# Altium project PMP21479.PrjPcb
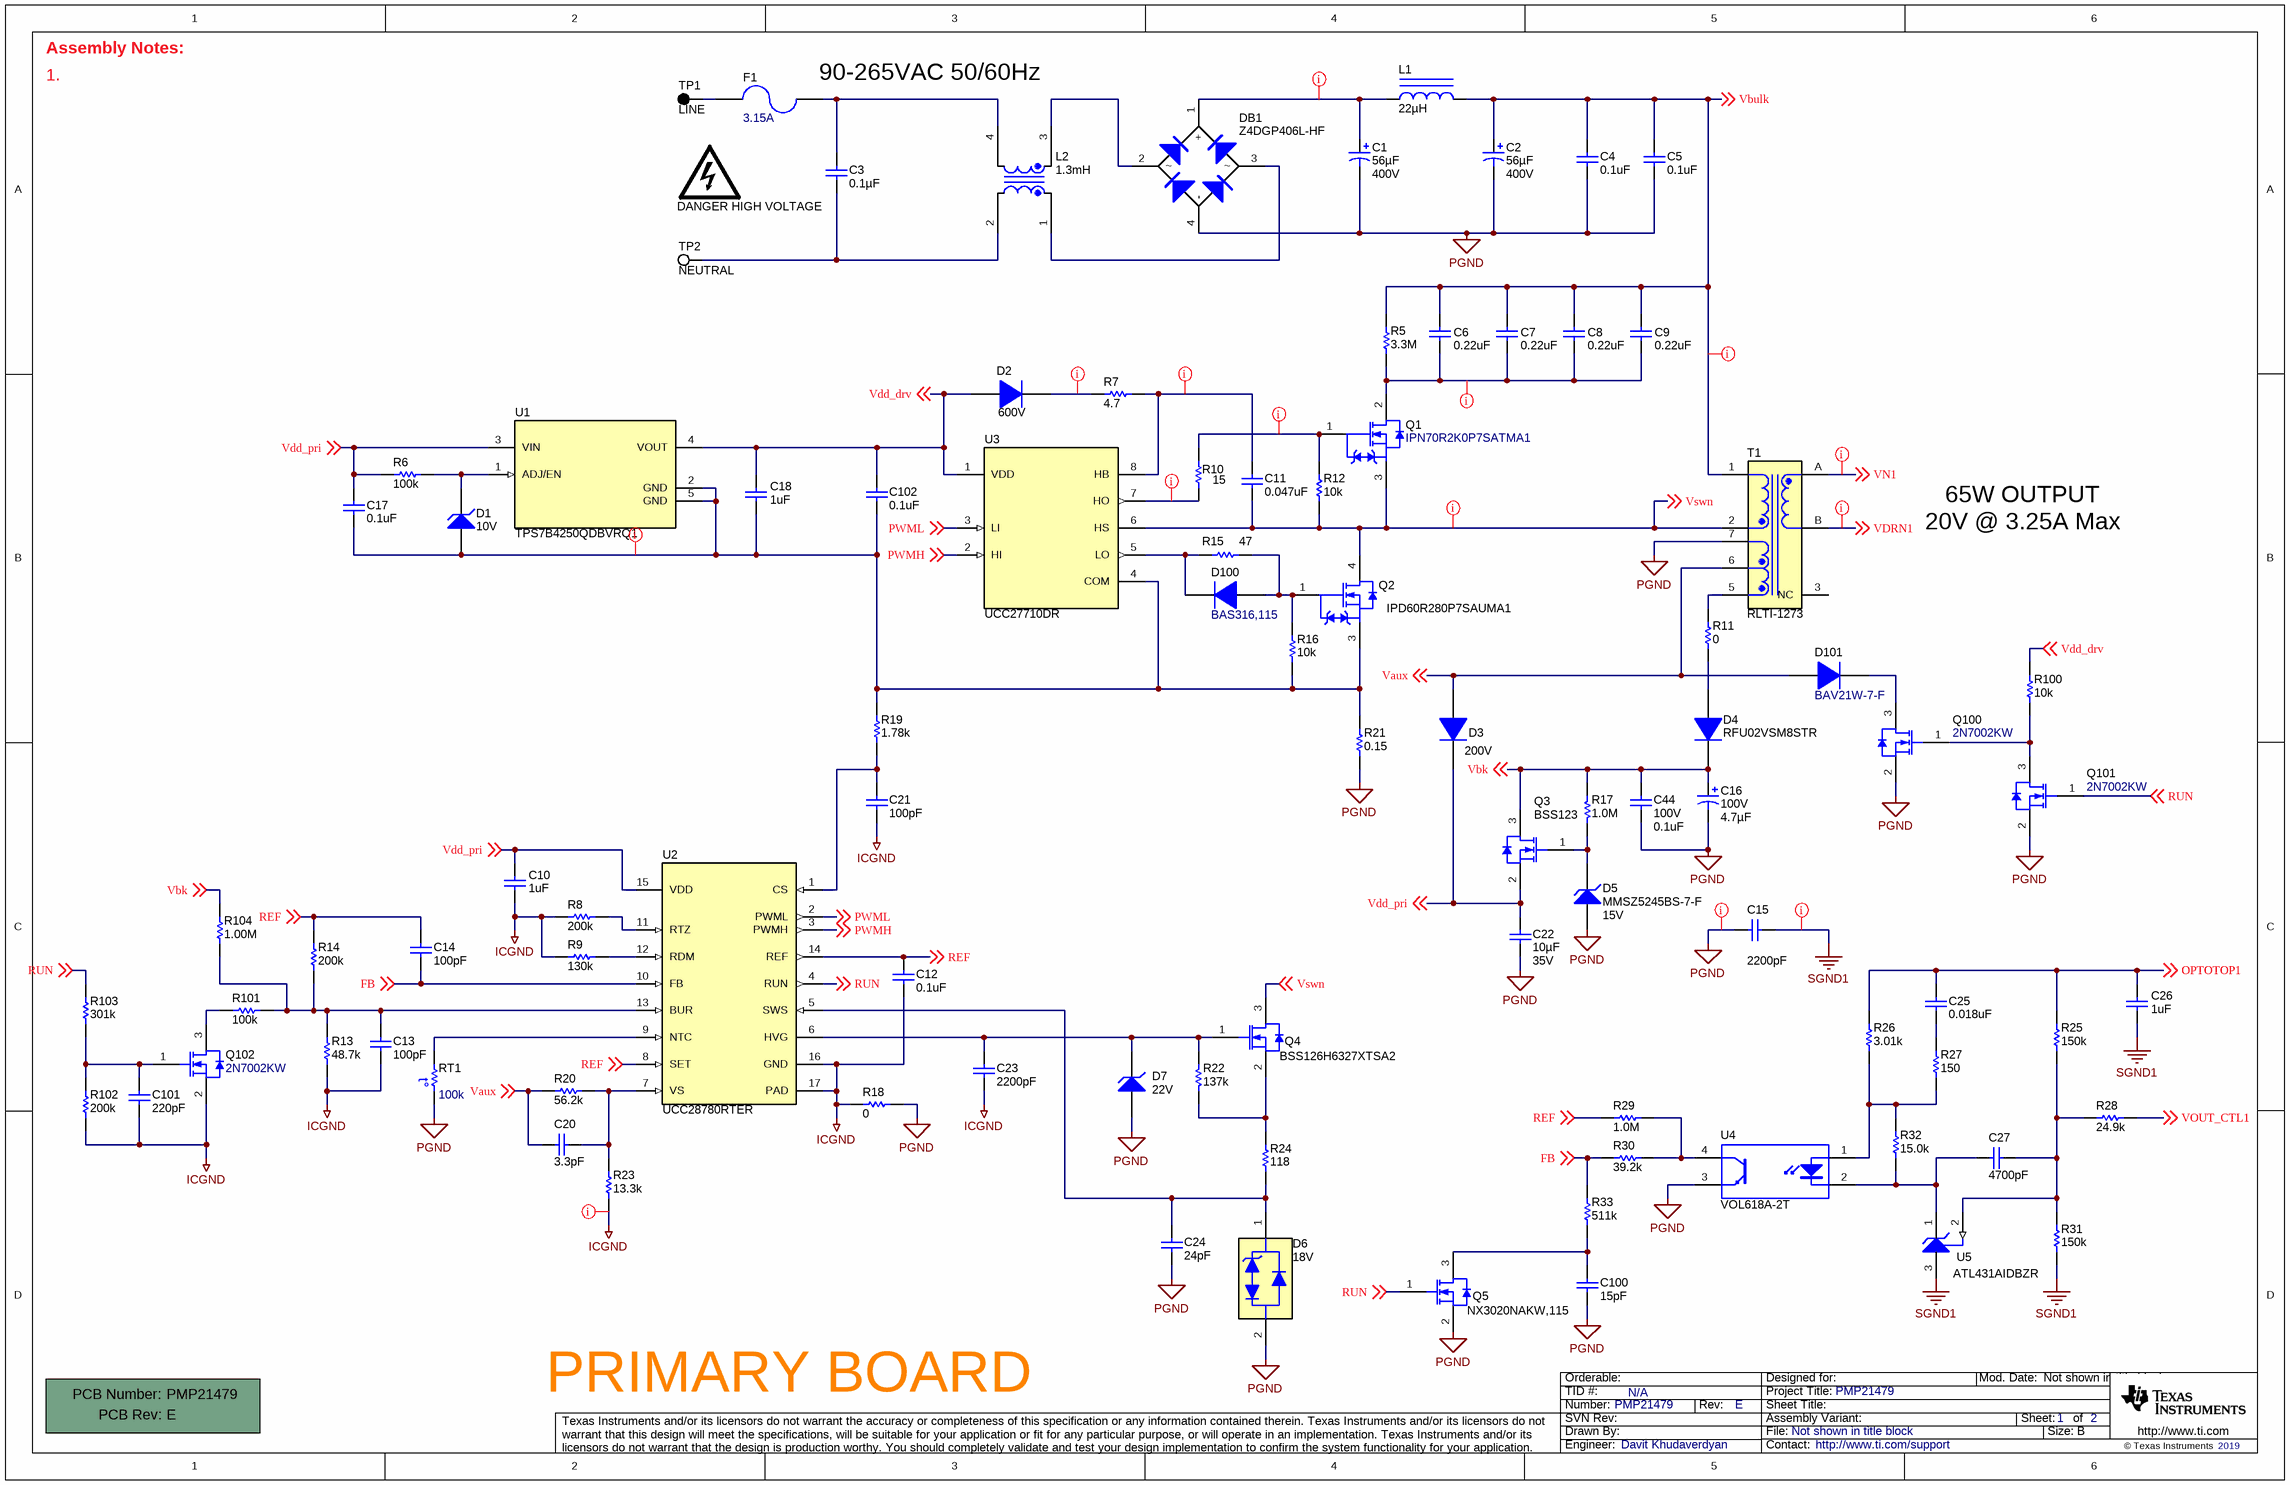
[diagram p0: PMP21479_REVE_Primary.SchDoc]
CopyrightYear: 2019; PCB_Layout: B King; PCB_Rev: E; PRJ_Engineer: Davit Khudaverdyan; PRJ_Number: PMP21479; PRJ_Title: PMP21479; SCH_Rev: E; TechSupport: http://www.ti.com/support; TID: N/A
2 sheets, 138 parts. Net scope: global (net labels, ports and power ports of the same name join across sheets).
Board file: PMP21479_PCBREVE.PcbDoc
Sheets:
  PMP21479_REVE_Primary.SchDoc
  PMP21479_REVE_Secondary.SchDoc

## Sheet PMP21479_REVE_Primary.SchDoc
size 431 x 279 mm; Date: Not shown in title block; ApprovedBy: Not shown in title block; CheckedBy: Not shown in title block; Author: Not shown in title block; CompanyName: Not shown in title block; Engineer: Not shown in title block; Organization: Not shown in title block; Address1: Not shown in title block; Address2: Not shown in title block; Address3: Not shown in title block; Address4: Not shown in title block; DocumentNumber: 1; Revision: Use project parameter SCH_Rev; SheetNumber: 1; SheetTotal: 2; PageSetup: Record=PageOptions¦CenterHorizontal=True¦CenterVertical=True¦PrintScale=1.00¦XCorrection=1.00¦YCorrection=1.00¦PrintKind=0¦BorderSize=5000000¦LeftOffset=0¦BottomOffset=0¦Orientation=2¦PaperLength=1000¦PaperWidth=1000¦Scale=100¦PaperSource=15¦PrintQuality=600¦MediaType=1¦DitherType=10¦PaperKind=Letter¦PrintScaleMode=1

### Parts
!PCB1  Printed Circuit Board  (value not drawn)  (mechanical)
C1  ValueDisplayed: 56µF  VDC_V: 400V  [UCY_1800x2000]  (hidden comment: UCY2G560MHD3)
C2  ValueDisplayed: 56µF  VDC_V: 400V  [UCY_1800x2000]  (hidden comment: UCY2G560MHD3)
C3  ValueDisplayed: 0.1µF  [WCAP-FTX2_1300x700x1300]  (hidden comment: 890324023023)
C4  ValueDisplayed: 0.1uF  [1210_280]  (hidden comment: C1210C104KBRAC7800)
C5  ValueDisplayed: 0.1uF  [1210_280]  (hidden comment: C1210C104KBRAC7800)
C6  ValueDisplayed: 0.22uF  [1210_220L]  (hidden comment: GRM32DR72E224KW01L)
C7  ValueDisplayed: 0.22uF  [1210_220L]  (hidden comment: GRM32DR72E224KW01L)
C8  ValueDisplayed: 0.22uF  [1210_220L]  (hidden comment: GRM32DR72E224KW01L)
C9  ValueDisplayed: 0.22uF  [1210_220L]  (hidden comment: GRM32DR72E224KW01L)
C10  ValueDisplayed: 1uF  [0603S]  (hidden comment: C1608X7R1E105K080AB)
C11  ValueDisplayed: 0.047uF  [0603S]  (hidden comment: GRM188R71E473KA01D)
C12  ValueDisplayed: 0.1uF  [0402S]  (hidden comment: C1005X7R1H104K050BB)
C13  ValueDisplayed: 100pF  [0402L]  (hidden comment: GRM1555C1H101JA01D)
C14  ValueDisplayed: 100pF  [0402L]  (hidden comment: GRM1555C1H101JA01D)
C15  ValueDisplayed: 2200pF  [DE1_900x400]  (hidden comment: DE1E3RA222MN4AN01F)
C16  VDC_V: 100V  ValueDisplayed: 4.7µF  [UPW_500x1100]  (hidden comment: UPS2A4R7MDD1TD)
C17  ValueDisplayed: 0.1uF  [0402S]  (hidden comment: GRM155R71E104KE14D)
C18  ValueDisplayed: 1uF  [0603S]  (hidden comment: C1608X7R1E105K080AB)
C20  ValueDisplayed: 3.3pF  [0402S]  (hidden comment: GRM1555C1H3R3CA01D)
C21  ValueDisplayed: 100pF  [0402L]  (hidden comment: GRM1555C1H101JA01D)
C22  ValueDisplayed: 10µF  Value2: 35V  [0805L]  (hidden comment: GRM21BC8YA106KE11L)
C23  ValueDisplayed: 2200pF  [0402S]  (hidden comment: GRM155R71H222KA01D)
C24  ValueDisplayed: 24pF  [0402S]  (hidden comment: GRM1555C1H240JA01D)
C25  ValueDisplayed: 0.018uF  [0402S]  (hidden comment: GRM155R71H183KA12D)
C26  ValueDisplayed: 1uF  [0603S]  (hidden comment: C1608X7R1E105K080AB)
C27  ValueDisplayed: 4700pF  [0402S]  (hidden comment: GRM155R71H472KA01D)
C44  VDC_V: 100V  ValueDisplayed: 0.1uF  [1206L]  (hidden comment: 12061C104JAT2A)
C100  ValueDisplayed: 15pF  [0402L]  (hidden comment: GRM1555C1H150JA01D)
C101  ValueDisplayed: 220pF  [0402L]  (hidden comment: GRM1555C1H221JA01D)
C102  ValueDisplayed: 0.1uF  [0402S]  (hidden comment: GRM155R71E104KE14D)
D1  value 10V  [SOD-323]  (hidden comment: MMSZ5240BS-7-F)
D2  value 600V  [SMAF]  (hidden comment: ES1JAF)
D3  value 200V  [SOD-123H]  (hidden comment: CSFMT104-HF)
D4  RFU02VSM8STR  [TUMD2SM]
D5  MMSZ5245BS-7-F  value 15V  [SOD-323]
D6  value 18V  [SOD-323]  (hidden comment: CDSOD323-T18)
D7  value 22V  [SOD-523]  (hidden comment: BZT52C22T-7)
D100  BAS316,115  [SOD-323]
D101  BAV21W-7-F  [SOD-123]
DB1  Z4DGP406L-HF  [Z4-D]
F1  3.15A  [FUSE_392]
L1  ValueDisplayed: 22µH  [NRS8030]  (hidden comment: NRS8030T220MJGJ)
L2  ValueDisplayed: 1.3mH  [Renco_RLTI-1301]  (hidden comment: RLTI-1301)
LOGO1  DANGER HIGH VOLTAGE  [IEC_HighVoltage_Small]  (no BOM)
Q1  IPN70R2K0P7SATMA1  [PG-SOT223]
Q2  IPD60R280P7SAUMA1  [DPAK]
Q3  BSS123  [SOT-23L]
Q4  BSS126H6327XTSA2  [SOT-23L]
Q5  NX3020NAKW,115  [SOT-323]
Q100  2N7002KW  [SOT-323]
Q101  2N7002KW  [SOT-323]
Q102  2N7002KW  [SOT-323]
R5  ValueDisplayed: 3.3M  [1206L]  (hidden comment: CRCW12063M30JNEA)
R6  ValueDisplayed: 100k  [0402L]  (hidden comment: RC0402FR-07100KL)
R7  ValueDisplayed: 4.7  [0402S]  (hidden comment: CRCW04024R70JNED)
R8  ValueDisplayed: 200k  [0402L]  (hidden comment: CRCW0402200KFKED)
R9  ValueDisplayed: 130k  [0402L]  (hidden comment: CRCW0402130KFKED)
R10  ValueDisplayed: 15  [0402S]  (hidden comment: CRCW040215R0JNED)
R11  ValueDisplayed: 0  [0402S]  (hidden comment: CRCW04020000Z0ED)
R12  ValueDisplayed: 10k  [0402S]  (hidden comment: CRCW040210K0JNED)
R13  ValueDisplayed: 48.7k  [0402L]  (hidden comment: CRCW040248K7FKED)
R14  ValueDisplayed: 200k  [0402L]  (hidden comment: CRCW0402200KFKED)
R15  ValueDisplayed: 47  [0805L]  (hidden comment: CRCW080547R0JNEA)
R16  ValueDisplayed: 10k  [0402S]  (hidden comment: CRCW040210K0JNED)
R17  ValueDisplayed: 1.0M  [0402S]  (hidden comment: CRCW04021M00JNED)
R18  ValueDisplayed: 0  [0402S]  (hidden comment: CRCW04020000Z0ED)
R19  ValueDisplayed: 1.78k  [0402S]  (hidden comment: CRCW04021K78FKED)
R20  ValueDisplayed: 56.2k  [0402S]  (hidden comment: CRCW040256K2FKED)
R21  ValueDisplayed: 0.15  [1206L]  (hidden comment: ERJ-8BSFR15V)
R22  ValueDisplayed: 137k  [0402S]  (hidden comment: ERJ-2RKF1373X)
R23  ValueDisplayed: 13.3k  [0402S]  (hidden comment: CRCW040213K3FKED)
R24  ValueDisplayed: 118  [0402S]  (hidden comment: CRCW0402118RFKED)
R25  ValueDisplayed: 150k  [0402S]  (hidden comment: ERJ-2RKF1503X)
R26  ValueDisplayed: 3.01k  [0402S]  (hidden comment: CRCW04023K01FKED)
R27  ValueDisplayed: 150  [0402S]  (hidden comment: CRCW0402150RFKED)
R28  ValueDisplayed: 24.9k  [0402S]  (hidden comment: CRCW040224K9FKED)
R29  ValueDisplayed: 1.0M  [0402S]  (hidden comment: CRCW04021M00JNED)
R30  ValueDisplayed: 39.2k  [0402S]  (hidden comment: CRCW040239K2FKED)
R31  ValueDisplayed: 150k  [0402S]  (hidden comment: ERJ-2RKF1503X)
R32  ValueDisplayed: 15.0k  [0402S]  (hidden comment: CRCW040215K0FKED)
R33  ValueDisplayed: 511k  [0402S]  (hidden comment: CRCW0402511KFKED)
R100  ValueDisplayed: 10k  [0402S]  (hidden comment: CRCW040210K0JNED)
R101  ValueDisplayed: 100k  [0402L]  (hidden comment: CRCW0402100KFKED)
R102  ValueDisplayed: 200k  [0402L]  (hidden comment: CRCW0402200KFKED)
R103  ValueDisplayed: 301k  [0402L]  (hidden comment: CRCW0402301KFKED)
R104  ValueDisplayed: 1.00M  [0402L]  (hidden comment: CRCW04021M00FKED)
RT1  value 100k  [0805L]  (hidden comment: NCP21WF104J03RA)
T1  RLTI-1273  [Renco_RLTI-1273]
TP1  LINE  [Keystone5011]
TP2  NEUTRAL  [Keystone5012]
U1  TPS7B4250QDBVRQ1  [DBV0005A_N]
U2  UCC28780RTER  [RTE0016C_NV]
U3  UCC27710DR  [D0008B_L]
U4  VOL618A-2T  [SOP254P1020X230-4]
U5  ATL431AIDBZR  [DBZ0003A_L]

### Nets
ICGND: C10.2 C12.2 C13.2 C21.2 C23.2 C101.2 Q102.2(S) R8.1 R9.1 R13.1 R18.2 R23.1 R102.1 U2.16(GND) U2.17(PAD)
PGND: C1.2(-) C2.2(-) C4.1 C5.1 C15.2 C16.2(-) C22.1 C24.1 C44.2 C100.2 D5.2(A) D6.2 D7.2(A) DB1.4(-) Q5.2(S) Q100.2(S) Q101.2(S) R18.1 R21.1 RT1.2 T1.7 U4.3(E)
SGND1: C15.1 C26.1 R31.2 U5.3(ANODE)
FB: C14.2 R30.1 R33.2 U2.10(FB) ; off-sheet FB
OPTOTOP1: C25.1 C26.2 R25.2 R26.2 ; off-sheet OPTOTOP1
PWMH: U2.3(PWMH) U3.2(HI) ; off-sheet PWMH
PWML: U2.2(PWML) U3.3(LI) ; off-sheet PWML
REF: C12.1 C14.1 R14.2 R29.2 U2.8(SET) U2.14(REF) ; off-sheet REF
RUN: Q5.1(G) Q101.1(G) R103.2 U2.4(RUN) ; off-sheet RUN
Vaux: C20.1 D3.2(A) D101.2(A) R20.2 T1.6 ; off-sheet Vaux
Vbk: C16.1(+) C44.1 D4.1(K) Q3.3(D) R17.1 R104.2 ; off-sheet Vbk
Vbulk: C2.1(+) C4.2 C5.2 C6.1 C7.1 C8.1 C9.1 L1.2 R5.2 T1.1 ; off-sheet Vbulk
Vdd_drv: C18.2 C102.1 D2.2(A) R100.2 U1.4(VOUT) U3.1(VDD) ; off-sheet Vdd_drv
Vdd_pri: C10.1 C17.1 C22.2 D3.1(K) Q3.2(S) R6.2 U1.3(VIN) U2.15(VDD) ; off-sheet Vdd_pri
VDRN1: T1.B ; off-sheet VDRN1
VN1: T1.A ; off-sheet VN1
VOUT_CTL1: R28.1 ; off-sheet VOUT_CTL1
Vswn: C11.2 Q1.3(S) Q2.4(D) Q4.3(D) R12.1 T1.2 U3.6(HS) ; off-sheet Vswn
NetC1_1: C1.1(+) DB1.1(+) L1.1
NetC3_1: C3.1 F1.1 L2.4
NetC3_2: C3.2 L2.2 TP2.1
NetC6_2: C6.2 C7.2 C8.2 C9.2 Q1.2(D) R5.1
NetC11_1: C11.1 R7.2 U3.8(HB)
NetC13_1: C13.1 R13.2 R14.1 R101.2 R104.1 U2.13(BUR)
NetC17_2: C17.2 C18.1 C102.2 D1.2(A) Q2.3(S) R16.1 R19.2 R21.2 U1.2(GND) U1.5(GND) U3.4(COM)
NetC20_2: C20.2 R20.1 R23.2 U2.7(VS)
NetC21_1: C21.1 R19.1 U2.1(CS)
NetC23_1: C23.1 D7.1(K) Q4.1(G) R22.2 U2.6(HVG)
NetC24_2: C24.2 D6.1 R24.1 U2.5(SWS)
NetC25_2: C25.2 R27.2
NetC27_1: C27.1 R25.1 R28.2 R31.1 U5.2(REF)
NetC27_2: C27.2 R32.1 U4.2(K) U5.1(CATHODE)
NetC100_1: C100.1 Q5.3(D) R33.1
NetC101_1: C101.1 Q102.1(G) R102.2 R103.1
NetD1_1: D1.1(K) R6.1 U1.1(ADJ/EN)
NetD2_1: D2.1(K) R7.1
NetD4_2: D4.2(A) R11.2
NetD5_1: D5.1(K) Q3.1(G) R17.2
NetD100_1: D100.1(K) R15.1 U3.5(LO)
NetD100_2: D100.2(A) Q2.1(G) R15.2 R16.2
NetD101_1: D101.1(K) Q100.3(D)
NetDB1_2: DB1.2 L2.3
NetDB1_3: DB1.3 L2.1
NetF1_2: F1.2 TP1.1
NetQ1_1: Q1.1(G) R10.2 R12.2
NetQ4_2: Q4.2(S) R22.1 R24.2
NetQ100_1: Q100.1(G) Q101.3(D) R100.1
NetQ102_3: Q102.3(D) R101.1
NetR8_2: R8.2 U2.11(RTZ)
NetR9_2: R9.2 U2.12(RDM)
NetR10_1: R10.1 U3.7(HO)
NetR11_1: R11.1 T1.5
NetR26_1: R26.1 R27.1 R32.2 U4.1(A)
NetR29_1: R29.1 R30.2 U4.4(C)
NetRT1_1: RT1.1 U2.9(NTC)

Not connected (* = marked no-connect by the designer): T1 3(NC)

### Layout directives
net class High Voltage: NetC1_1, NetC6_2, NetC11_1, NetD2_1, NetQ1_1, NetR10_1, Vbulk, Vswn
net class Secondary: SGND1, VDRN1, VN1
net class Primary: ICGND, NetC17_2, PGND

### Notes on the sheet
- 1.
- Assembly Notes:
- (near F1) 90-265VAC 50/60Hz
- 65W OUTPUT
- 20V @ 3.25A Max
- PRIMARY BOARD

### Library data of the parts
!PCB1 = CMP-0003618-2: Manufacturer: Any; PartNumber: PMP21479
C1 C2 = CMP-0086273-1: CAP, AL, 56 µF, 400 V, +/- 20%, AEC-Q200 Grade 2, TH; Manufacturer: Nichicon; Cap_Case: 18x20mm; SizeZ_mm: 21.5; TaMax_C: 105°C; SizeY_mm: 18; Value: 56uF; Polarized: Y; TaMin_C: -40°C; U/M: EA; CompType: Capacitor; AEC Grade: 2; AEC Category: Q200; SizeArea_mm2: 324; SizeAreaWB_mm2: 400
C3 = CMP-0081647-1: CAP, Film, 0.1 µF,  V,+/- 10%, TH; Manufacturer: Wurth Elektronik; Cap_F: 100nF; SizeAreaWB_mm2: 135; SizeArea_mm2: 91; AEC Qualified: N; AEC Category: Q200; Value: 0.1uF; TaMax_C: 105°C; SizeZ_mm: 13.5; TaMin_C: -40°C; SizeY_mm: 7; SizeX_mm: 13; Cap_Case: 13x7x13mm
C4 C5 = CMP-0009076-1: CAP, CERM, 0.1 uF, 630 V, +/- 10%, X7R, 1210; Manufacturer: Kemet; Polarized: N; CompType: Capacitor; Value: 0.1uF; U/M: EA; Cap_F: 100nF; Value1: Unknown; VDC_V: 630V; TaMin_C: -55°C; TaMax_C: 125°C; Cap_Case: 1210; SizeArea_mm2: 8; SizeAreaWB_mm2: 14.7; SizeX_mm: 3.2; SizeY_mm: 2.5; SizeZ_mm: 2.8; AEC Category: Q200
C6-C9 = CMP-0009193-2: CAP, CERM, 0.22 uF, 250 V, +/- 10%, X7R, 1210; Manufacturer: MuRata; Polarized: N; CompType: Capacitor; Value: 0.22uF; U/M: EA; Cap_F: 220nF; Value1: Unknown; VDC_V: 250V; TaMin_C: -55°C; TaMax_C: 125°C; Cap_Case: 1210; SizeArea_mm2: 8; SizeAreaWB_mm2: 14.7; SizeX_mm: 3.2; SizeY_mm: 2.5; SizeZ_mm: 2.2; AEC Category: Q200
C10 C18 C26 = CMP-0007040-4: CAP, CERM, 1 uF, 25 V, +/- 10%, X7R, 0603; Manufacturer: TDK; Polarized: N; CompType: Capacitor; Value: 1uF; U/M: EA; Cap_F: 1µF; Value1: Unknown; VDC_V: 25V; TaMin_C: -55°C; TaMax_C: 125°C; Cap_Case: 0603; AEC Category: Q200; SizeArea_mm2: 1.28; SizeAreaWB_mm2: 4.68; SizeX_mm: 1.6; SizeY_mm: 0.8; SizeZ_mm: 1
C11 = CMP-0007423-4: CAP, CERM, 0.047 uF, 25 V, +/- 10%, X7R, 0603; Manufacturer: MuRata; TaMin_C: -55°C; Polarized: N; SizeAreaWB_mm2: 4.68; Value1: Unknown; U/M: EA; TaMax_C: 125°C; SizeZ_mm: 1; SizeX_mm: 1.6; SizeY_mm: 0.8; Cap_Case: 0603; Value2: 25V; SizeArea_mm2: 1.28; CompType: Capacitor; Cap_F: 47nF; AEC Category: Q200
C12 = CMP-0006297-2: CAP, CERM, 0.1 uF, 50 V, +/- 10%, X7R, 0402; Manufacturer: TDK; TaMin_C: -55°C; ESR_ohm: 0.039064; Polarized: N; SizeAreaWB_mm2: 3; Value1: 0.039064 ohm; U/M: EA; Value: 0.1uF; TaMax_C: 125°C; SizeZ_mm: 0.6; SizeX_mm: 1; SizeY_mm: 0.5; Cap_Case: 0402; Value2: 50V; CompType: Capacitor; Cap_F: 100nF; IRMS_A: 8.14669dA; AEC Category: Q200
C13 C14 C21 = CMP-0006410-2: CAP, CERM, 100 pF, 50 V, +/- 5%, C0G/NP0, 0402; Manufacturer: MuRata; TaMin_C: -55°C; Polarized: N; SizeAreaWB_mm2: 3; Value1: Unknown; U/M: EA; Value: 100pF; TaMax_C: 125°C; SizeZ_mm: 0.6; SizeX_mm: 1; SizeY_mm: 0.5; Cap_Case: 0402; Value2: 50V; AEC Category: Q200
C15 = CMP-0086279-1: CAP, CERM, 2200 pF, 250 V,+/- 20%, E, Dia 9mm; Manufacturer: MuRata; SizeX_mm: 10.6; AEC Qualified: N; SizeY_mm: 4; Value: 2200pF; U/M: EA; AEC Category: Q200; TaMax_C: 125°C; Cap_Case: 9x4mm; VDC_V: 250V; Polarized: Y; SizeZ_mm: 12; TaMin_C: -40°C; SizeArea_mm2: 42.4; SizeAreaWB_mm2: 75.6; Cap_F: 2.2nF
C16 = CMP-0084595-1: CAP, AL, 4.7 µF, 100 V, +/- 20%, TH; Manufacturer: Nichicon; Cap_Case: 5x11mm; SizeArea_mm2: 25; Value: 4.7uF; Polarized: Y; SizeAreaWB_mm2: 49; CompType: Capacitor; SizeX_mm: 5; TaMin_C: -55°C; AEC Category: Q200; SizeZ_mm: 12.5; TaMax_C: 105°C; AEC Qualified: N; U/M: EA
C17 C102 = CMP-0006659-2: CAP, CERM, 0.1 uF, 25 V, +/- 10%, X7R, 0402; Manufacturer: MuRata; TaMin_C: -55°C; Polarized: N; SizeAreaWB_mm2: 3; Value1: Unknown; U/M: EA; Value: 0.1uF; TaMax_C: 125°C; SizeZ_mm: 0.6; SizeX_mm: 1; SizeY_mm: 0.5; Cap_Case: 0402; Value2: 25V; CompType: Capacitor; Cap_F: 100nF; AEC Category: Q200
C20 = CMP-0006462-2: CAP, CERM, 3.3 pF, 50 V, +/- 5%, C0G/NP0, 0402; Manufacturer: MuRata; TaMin_C: -55°C; Polarized: N; SizeAreaWB_mm2: 3; Value1: Unknown; U/M: EA; Value: 3.3pF; TaMax_C: 125°C; SizeZ_mm: 0.6; SizeX_mm: 1; SizeY_mm: 0.5; Cap_Case: 0402; Value2: 50V; CompType: Capacitor; AEC Category: Q200
C22 = C2012JB1V226M125AC: CAP, CERM, 10 µF, 35 V, +/- 10%, X6S, 0805; Manufacturer: TDK; Polarized: N; CompType: Capacitor; Value: 22uF; U/M: EA; Cap_F: 0.000022; Tolerance_%: 20; Value1: Unknown; VDC_V: 35; TaMin_C: -25; TaMax_C: 85; Cap_Case: 0805; SizeAreaWB_mm2: 6.75; SizeArea_mm2: 2.5; SizeX_mm: 2; SizeY_mm: 1.25; SizeZ_mm: 1.45; AEC Category: Q200
C23 = CMP-0006683-2: CAP, CERM, 2200 pF, 50 V, +/- 10%, X7R, 0402; Manufacturer: MuRata; TaMin_C: -55°C; Polarized: N; SizeAreaWB_mm2: 3; Value1: Unknown; U/M: EA; Value: 2200pF; TaMax_C: 125°C; SizeZ_mm: 0.6; SizeX_mm: 1; SizeY_mm: 0.5; Cap_Case: 0402; Value2: 50V; CompType: Capacitor; Cap_F: 2.2nF; AEC Category: Q200
C24 = CMP-0006441-2: CAP, CERM, 24 pF, 50 V, +/- 5%, C0G/NP0, 0402; Manufacturer: MuRata; TaMin_C: -55°C; Polarized: N; SizeAreaWB_mm2: 3; Value1: Unknown; U/M: EA; Value: 24pF; TaMax_C: 125°C; SizeZ_mm: 0.6; SizeX_mm: 1; SizeY_mm: 0.5; Cap_Case: 0402; Value2: 50V; CompType: Capacitor; AEC Category: Q200
C25 = CMP-0006681-2: CAP, CERM, 0.018 uF, 50 V, +/- 10%, X7R, 0402; Manufacturer: MuRata; TaMin_C: -55°C; Polarized: N; SizeAreaWB_mm2: 3; Value1: Unknown; U/M: EA; TaMax_C: 125°C; SizeZ_mm: 0.6; SizeX_mm: 1; SizeY_mm: 0.5; Cap_Case: 0402; Value2: 50V; Cap_F: 18nF; AEC Category: Q200
C27 = CMP-0006692-2: CAP, CERM, 4700 pF, 50 V, +/- 10%, X7R, 0402; Manufacturer: MuRata; TaMin_C: -55°C; Polarized: N; SizeAreaWB_mm2: 3; Value1: Unknown; U/M: EA; Value: 4700pF; TaMax_C: 125°C; SizeZ_mm: 0.6; SizeX_mm: 1; SizeY_mm: 0.5; Cap_Case: 0402; Value2: 50V; Cap_F: 4.7nF; AEC Category: Q200
C44 = CMP-0008487-2: CAP, CERM, 0.1 uF, 100 V, +/- 5%, X7R, 1206; Manufacturer: AVX; TaMin_C: -55°C; ESR_ohm: 0.037; Polarized: N; SizeAreaWB_mm2: 10.92; Value1: 0.037 ohm; U/M: EA; Value: 0.1uF; TaMax_C: 125°C; SizeZ_mm: 1.35; SizeX_mm: 3.2; SizeY_mm: 1.6; Cap_Case: 1206; SizeArea_mm2: 5.12; CompType: Capacitor; Cap_F: 100nF; AEC Category: Q200
C100 = CMP-0006420-2: CAP, CERM, 15 pF, 50 V, +/- 5%, C0G/NP0, 0402; Manufacturer: MuRata; TaMin_C: -55°C; Polarized: N; SizeAreaWB_mm2: 3; Value1: Unknown; U/M: EA; Value: 15pF; TaMax_C: 125°C; SizeZ_mm: 0.6; SizeX_mm: 1; SizeY_mm: 0.5; Cap_Case: 0402; Value2: 50V; AEC Category: Q200
C101 = CMP-0006440-2: CAP, CERM, 220 pF, 50 V, +/- 5%, C0G/NP0, 0402; Manufacturer: MuRata; TaMin_C: -55°C; Polarized: N; SizeAreaWB_mm2: 3; Value1: Unknown; U/M: EA; Value: 220pF; TaMax_C: 125°C; SizeZ_mm: 0.6; SizeX_mm: 1; SizeY_mm: 0.5; Cap_Case: 0402; Value2: 50V; AEC Category: Q200
D1 = CMP-0005829-1: Diode, Zener, 10 V, 200 mW, SOD-323; Manufacturer: Diodes Inc.; Power_W: 200mW; SizeAreaWB_mm2: 8.695; Value1: 0.2W; RJA_CperW: 350; U/M: EA; SizeZ_mm: 1; SizeX_mm: 2.7; SizeY_mm: 1.35; SizeArea_mm2: 3.645; AEC Category: Q101
D2 = CMP-0029162-1: Diode, Ultrafast, 600 V, 1 A, AEC-Q101, SMAF; Manufacturer: Fairchild Semiconductor; Io_A: 1A; Green_Lifecycle: Not Set; SizeAreaWB_mm2: 19.95; Green_REACh: Incomplete; TJmax_C: 150°C; U/M: EA; SizeZ_mm: 1; SizeX_mm: 4.7; SizeY_mm: 2.5; Vf_V: 1.7V; SizeArea_mm2: 11.75; AEC Qualified: Y; AEC Category: Q101
D3 = CMP-0029199-1: Diode, Superfast Rectifier, 200 V, 1 A, 3.5x1.6mm; Manufacturer: Comchip Technology; U/M: EA; Vf_V: 9.5dV; Value1: 1A; Value2: 0.95V; TJmax_C: 150°C; SizeAreaWB_mm2: 11.7; SizeArea_mm2: 5.6; SizeX_mm: 3.5; SizeY_mm: 1.6; SizeZ_mm: 1; AEC Category: Q101; AEC Qualified: N
D4 = CMP-0077868-1: Diode, Standard Recovery Rectifier, 800 V, .2 A, 2x1.4mm; Manufacturer: Rohm; SizeAreaWB_mm2: 8.4; Vr_V: 800V; SizeArea_mm2: 3.5; AEC Qualified: N; TJmax_C: 150°C; AEC Category: Q101; Value: 800V; SizeZ_mm: 0.8; Io_A: 2dA; Vf_V: 2.2V; SizeY_mm: 1.4; Value1: .2A; SizeX_mm: 2.5
D5 = CMP-0005833-2: Diode, Zener, 15 V, 200 mW, SOD-323; Manufacturer: Diodes Inc.; Power_W: 200mW; SizeAreaWB_mm2: 8.695; Value1: 0.2W; RJA_CperW: 350; U/M: EA; SizeZ_mm: 1; SizeX_mm: 2.7; SizeY_mm: 1.35; SizeArea_mm2: 3.645; AEC Category: Q101
D6 = CMP-0065112-2: Diode, TVS, Uni, 18 V, 45 Vc, SOD-323; Manufacturer: Bourns; U/M: EA; Value1: W; SizeAreaWB_mm2: 8.695; SizeArea_mm2: 3.645; SizeX_mm: 2.7; SizeY_mm: 1.35; SizeZ_mm: 1.0; AEC Category: Q101; AEC Qualified: N
D7 = CMP-0005884-3: Diode, Zener, 22 V, 300 mW, SOD-523; Manufacturer: Diodes Inc.; U/M: EA; Power_W: 300mW; Value1: 0.3W; RJA_CperW: 417; SizeAreaWB_mm2: 5.13; SizeArea_mm2: 1.53; SizeX_mm: 1.7; SizeY_mm: 0.9; SizeZ_mm: 0.65; AEC Category: Q101
D100 = CMP-0029006-2: Diode, Ultrafast, 100 V, 0.25 A, SOD-323; Manufacturer: Nexperia; SizeY_mm: 1.35; Value1: 0.25A; SizeAreaWB_mm2: 8.695; SizeZ_mm: 1; Io_A: 250mA; Value2: 1.4V; SizeX_mm: 2.7; Green_REACh: Incomplete; TJmax_C: 150°C; Green_Lifecycle: Not Set; Vr_V: 100V; AEC Category: Q101; Value: 100V; SizeArea_mm2: 3.645
D101 = CMP-0029031-1: Diode, Switching, 200 V, 0.2 A, SOD-123; Manufacturer: Diodes Inc.; Io_A: 200mA; Green_Lifecycle: Active; SizeAreaWB_mm2: 13.095; Vr_V: 200V; Green_REACh: Passed; Value1: 0.2A; TJmax_C: 150°C; U/M: EA; Value: 200V; SizeZ_mm: 1.35; SizeX_mm: 3.85; SizeY_mm: 1.7; Vf_V: 1.25V; SizeArea_mm2: 6.545; AEC Category: Q101
DB1 = Z4DGP406L-HF: Diode, P-N-Bridge, 600 V, 4 A, Z4-D; Manufacturer: Comchip Technology; U/M: EA; Vf_V: 0.95; Value: 600V; Value1: 4A; Value2: 0.95V; Io_A: 4; Vr_V: 600; TJmax_C: 175; SizeAreaWB_mm2: 126.25; SizeArea_mm2: 85.05; SizeX_mm: 10.5; SizeY_mm: 8.1; SizeZ_mm: 1.55; AEC Category: Q101; AEC Qualified: N; Green_Lifecycle: Not Set; Green_REACh: Incomplete
F1 = CMP-0003561-2: Fuse, 3.15 A, 250VAC/VDC, TH; Manufacturer: Littelfuse; PartNumber: 39213150000; VAC_V: 250V
L1 = CMP-0084605-1: Inductor, Shielded, Ferrite, 22 µH, 1.75 A, 0.091 ohm, SMD; Manufacturer: Taiyo Yuden; Value: 22uH; SizeZ_mm: 3; SizeAreaWB_mm2: 100; Isat: 1.75A @ 30% inductance drop; DCR_ohm: 0.091; Value2: 1.75A; Irms: 1.9A @ 40C rise; SizeArea_mm2: 64; AEC Category: Q200; SizeY_mm: 8; AEC Qualified: N
L2 = CMP-0086351-1: Coupled inductor, 1.3 mH, 0.035 ohm, TH; Manufacturer: Renco Electronics; SizeY_mm: 15.24; DCR_ohm: 0.035; AEC Category: Q200; AEC Qualified: N; SizeX_mm: 9.906; Value: 1.3mH; SizeAreaWB_mm2: 205.25944; SizeZ_mm: 18.415; SizeArea_mm2: 150.96744
LOGO1 = IEC_HighVoltage: IEC 61010-1 High Voltage Warning; SymbolCreator: a0412235
Q1 = CMP-0086300-1: MOSFET, N-CH, 700 V, 30 A, PG-SOT223; Alternate Manufacturer: None; Manufacturer: Infineon Technologies; SizeArea_mm2: 45.5; IdsMax_A: 30A; AEC Qualified: N; SizeY_mm: 6.5; QgTyp_nC: 3.8; ChMode: Enhancement; VdsMax_V: 700V; AEC Category: Q101; SizeX_mm: 7; SizeZ_mm: 1.8; SizeAreaWB_mm2: 76.5; Vgs_V: 16V; Value1: ? ohm; Value: 700V; Value2: 3.8 nC
Q2 = CMP-0079238-1: MOSFET, N-CH, 600 V, 12 A, DPAK; Manufacturer: Infineon Technologies; Alternate Manufacturer: None; ChType: N; QgTyp_nC: 18; SizeAreaWB_mm2: 101.7114; SizeArea_mm2: 64.8114; IdsMax_A: 12A; VdsMax_V: 600V; Vgs_V: 20V; AEC Category: Q101; Value: 600V; SizeZ_mm: 2.29; SizeY_mm: 6.54; Value2: 18 nC; U/M: EA; Value1: ? ohm; SizeX_mm: 9.91
Q3 = BSS123: MOSFET, N-CH, 100 V, 0.17 A, SOT-23; Manufacturer: Fairchild Semiconductor; Alternate Manufacturer: None; U/M: EA; ChType: N; Value: 100V; VdsMax_V: 100; Value1: 10 ohm; Rdson45_ohm: 10; Value2: 1.8 nC; QgTyp_nC: 1.8; Vgs_V: 20; IdsMax_A: 0.17; SizeAreaWB_mm2: 14; SizeArea_mm2: 7.5; SizeX_mm: 2.5; SizeY_mm: 3; SizeZ_mm: 1.1; AEC Category: Q101; Green_Lifecycle: Active; Green_REACh: Passed
Q4 = CMP-0067574-1: MOSFET, N-CH, 600 V, 0.021 A, AEC-Q101, SOT-23; Manufacturer: Infineon Technologies; Alternate Manufacturer: None; U/M: EA; ChType: N; Value: 600V; Value1: ? ohm; Value2: 1.4 nC; QgTyp_nC: 1.4; Vgs_V: 20V; IdsMax_A: 21mA; SizeAreaWB_mm2: 14.0; SizeArea_mm2: 7.5; SizeX_mm: 2.5; SizeY_mm: 3.0; SizeZ_mm: 1.1; AEC Category: Q101; AEC Qualified: Y
Q5 = CMP-0000643-1: MOSFET, N-CH, 30 V, 0.18 A, SOT-323; Manufacturer: NXP Semiconductor; Alternate Manufacturer: None; U/M: EA; ChType: N; Value: 30V; Value1: 5; Rdson45_ohm: 5.2; Value2: 0.34 nC; QgTyp_nC: 0.34; Vgs_V: 20V; IdsMax_A: 1.8dA; SizeAreaWB_mm2: 10.24; SizeArea_mm2: 4.84; SizeX_mm: 2.2; SizeZ_mm: 1.1; AEC Category: Q101
Q100-Q102 = CMP-0000774-1: MOSFET, N-CH, 60 V, 0.31 A, SOT-323; Alternate Manufacturer: None; Manufacturer: Fairchild Semiconductor; SizeZ_mm: 1.1; ChType: N; Value1: 1; VdsMax_V: 60V; SizeX_mm: 2.2; Vgs_V: 2.1V; Value: 60V; Rdson45_ohm: 1.6; SizeArea_mm2: 4.84; AEC Category: Q101; IdsMax_A: 310mA; SizeAreaWB_mm2: 10.24; U/M: EA
R5 = CMP-0018673-3: RES, 3.3 M, 5%, 0.25 W, AEC-Q200 Grade 0, 1206; Manufacturer: Vishay-Dale; CompType: Resistor; Value: 3.3Meg; Value_Code: 3M30; Power_W: 250mW; Value2: 0.25W; VDC_V: 200V; TempCo: 200 ppm/C; SizeArea_mm2: 5.12; SizeX_mm: 3.2; SizeY_mm: 1.6; SizeZ_mm: 1.35; EIA_Code: E24; AEC Category: Q200; AEC Qualified: Y; AEC Grade: 0
R6 = CMP-0026721-1: RES, 100 k, 1%, 0.0625 W, 0402; Manufacturer: Yageo America; Power_W: 62.5mW; TempCo: 100 ppm/C; U/M: EA; Value: 100k; EIA_Code: E96; SizeX_mm: 1; SizeY_mm: 0.5; SizeZ_mm: 0.6; CompType: Resistor; AEC Qualified: N; VDC_V: 50V; AEC Category: Q200
R7 = CMP-0026942-3: RES, 4.7, 5%, 0.063 W, AEC-Q200 Grade 0, 0402; Manufacturer: Vishay-Dale; Power_W: 63mW; TempCo: 200 ppm/C; Value_Code: 4R70; Value: 4.7; EIA_Code: E24; SizeX_mm: 1; SizeY_mm: 0.5; SizeZ_mm: 0.6; Value2: 0.063W; CompType: Resistor; AEC Qualified: Y; VDC_V: 50V; AEC Category: Q200; AEC Grade: 0
R8 R14 R102 = CMP-0026158-2: RES, 200 k, 1%, 0.063 W, AEC-Q200 Grade 0, 0402; Manufacturer: Vishay-Dale; Power_W: 63mW; TempCo: 100 ppm/C; Value: 200k; EIA_Code: E96; SizeX_mm: 1; SizeY_mm: 0.5; SizeZ_mm: 0.6; Value2: 0.063W; AEC Qualified: Y; VDC_V: 50V; AEC Category: Q200; AEC Grade: 0
R9 = CMP-0025997-3: RES, 130 k, 1%, 0.063 W, AEC-Q200 Grade 0, 0402; Manufacturer: Vishay-Dale; Power_W: 63mW; TempCo: 100 ppm/C; Value: 130k; EIA_Code: E96; SizeX_mm: 1; SizeY_mm: 0.5; SizeZ_mm: 0.6; Value2: 0.063W; AEC Qualified: Y; VDC_V: 50V; AEC Category: Q200; AEC Grade: 0
R10 = CMP-0026843-3: RES, 15, 5%, 0.063 W, AEC-Q200 Grade 0, 0402; Manufacturer: Vishay-Dale; Power_W: 63mW; TempCo: 200 ppm/C; Value_Code: 15R0; Value: 15; EIA_Code: E24; SizeX_mm: 1; SizeY_mm: 0.5; SizeZ_mm: 0.6; Value2: 0.063W; CompType: Resistor; AEC Qualified: Y; VDC_V: 50V; AEC Category: Q200; AEC Grade: 0
R11 R18 = CMP-0026822-3: RES, 0, 5%, 0.063 W, AEC-Q200 Grade 0, 0402; Manufacturer: Vishay-Dale; Power_W: 63mW; TempCo: 200 ppm/C; Value_Code: 0000; Value: 0; EIA_Code: E24; SizeX_mm: 1; SizeY_mm: 0.5; SizeZ_mm: 0.6; Value2: 0.063W; CompType: Resistor; AEC Qualified: Y; VDC_V: 50V; AEC Category: Q200
R12 R16 R100 = CMP-0026825-5: RES, 10 k, 5%, 0.063 W, AEC-Q200 Grade 0, 0402; Manufacturer: Vishay-Dale; Power_W: 63mW; TempCo: 200 ppm/C; Value_Code: 10k0; Value: 10k; EIA_Code: E24; SizeX_mm: 1; SizeY_mm: 0.5; SizeZ_mm: 0.6; Value2: 0.063W; CompType: Resistor; AEC Qualified: Y; VDC_V: 50V; AEC Category: Q200; AEC Grade: 0
R13 = CMP-0026399-2: RES, 48.7 k, 1%, 0.063 W, AEC-Q200 Grade 0, 0402; Manufacturer: Vishay-Dale; Power_W: 63mW; TempCo: 100 ppm/C; Value_Code: 48k7; Value: 48.7k; EIA_Code: E96; SizeX_mm: 1; SizeY_mm: 0.5; SizeZ_mm: 0.6; Value2: 0.063W; AEC Qualified: Y; VDC_V: 50V; AEC Category: Q200; AEC Grade: 0
R15 = CMP-0020557-3: RES, 47, 5%, 0.125 W, AEC-Q200 Grade 0, 0805; Manufacturer: Vishay-Dale; Power_W: 125mW; TempCo: 200 ppm/C; Value_Code: 47R0; Value: 47; EIA_Code: E24; SizeX_mm: 2; SizeY_mm: 1.25; SizeZ_mm: 1.45; Value2: 0.125W; SizeArea_mm2: 2.5; AEC Qualified: Y; VDC_V: 150V; AEC Category: Q200; AEC Grade: 0
R17 = CRCW04021M00JNED: RES, 1.0 M, 5%, 0.063 W, 0402; Manufacturer: Vishay-Dale; CompType: Resistor; Value: 1.0Meg; Res_ohm: 1000000; Value_Code: 1M00; Tolerance_%: 5; Power_W: 0.063; Value2: 0.063W; VDC_V: 50; TempCo: 200 ppm/C; SizeArea_mm2: 0.5; SizeX_mm: 1; SizeZ_mm: 0.6; EIA_Code: E24; U/M: EA; AEC Category: Q200; Green_Lifecycle: Active; Green_REACh: Passed
R19 = CMP-0026095-2: RES, 1.78 k, 1%, 0.063 W, AEC-Q200 Grade 0, 0402; Manufacturer: Vishay-Dale; Power_W: 63mW; TempCo: 100 ppm/C; Value_Code: 1k78; Value: 1.78k; EIA_Code: E96; SizeX_mm: 1; SizeY_mm: 0.5; SizeZ_mm: 0.6; Value2: 0.063W; CompType: Resistor; AEC Qualified: Y; VDC_V: 50V; AEC Category: Q200; AEC Grade: 0
R20 = CMP-0026453-2: RES, 56.2 k, 1%, 0.063 W, AEC-Q200 Grade 0, 0402; Manufacturer: Vishay-Dale; Power_W: 63mW; TempCo: 100 ppm/C; Value_Code: 56k2; Value: 56.2k; EIA_Code: E96; SizeX_mm: 1; SizeY_mm: 0.5; SizeZ_mm: 0.6; Value2: 0.063W; CompType: Resistor; AEC Qualified: Y; VDC_V: 50V; AEC Category: Q200; AEC Grade: 0
R21 = CMP-0017277-2: RES, 0.15, 1%, 0.5 W, 1206; Manufacturer: Panasonic; Power_W: 500mW; TempCo: 250 ppm/C; Value_Code: R150; U/M: EA; Value: 0.15; EIA_Code: E96; Res_ohm: 1.5d; SizeX_mm: 3.2; SizeY_mm: 1.6; SizeZ_mm: 1.35; Value2: 0.5W; SizeArea_mm2: 5.12; CompType: Resistor; AEC Qualified: N; AEC Category: Q200
R22 = CMP-0026665-1: RES, 137 k, 1%, 0.1 W, AEC-Q200 Grade 0, 0402; Manufacturer: Panasonic; Power_W: 100mW; TempCo: 100 ppm/C; U/M: EA; Value: 137k; EIA_Code: E96; SizeX_mm: 1; SizeY_mm: 0.5; SizeZ_mm: 0.6; Value2: 0.1W; CompType: Resistor; AEC Qualified: Y; VDC_V: 50V; AEC Grade: 0; AEC Category: Q200
R23 = CMP-0026004-3: RES, 13.3 k, 1%, 0.063 W, AEC-Q200 Grade 0, 0402; Manufacturer: Vishay-Dale; Power_W: 63mW; TempCo: 100 ppm/C; Value_Code: 13k3; Value: 13.3k; EIA_Code: E96; SizeX_mm: 1; SizeY_mm: 0.5; SizeZ_mm: 0.6; Value2: 0.063W; CompType: Resistor; AEC Qualified: Y; VDC_V: 50V; AEC Category: Q200; AEC Grade: 0
R24 = CMP-0025974-3: RES, 118, 1%, 0.063 W, AEC-Q200 Grade 0, 0402; Manufacturer: Vishay-Dale; Power_W: 63mW; TempCo: 100 ppm/C; Value_Code: 118R; Value: 118; EIA_Code: E96; SizeX_mm: 1; SizeY_mm: 0.5; SizeZ_mm: 0.6; Value2: 0.063W; CompType: Resistor; AEC Qualified: Y; VDC_V: 50V; AEC Category: Q200; AEC Grade: 0
R25 R31 = CMP-0026669-1: RES, 150 k, 1%, 0.1 W, AEC-Q200 Grade 0, 0402; Manufacturer: Panasonic; Power_W: 100mW; TempCo: 100 ppm/C; U/M: EA; Value: 150k; EIA_Code: E96; SizeX_mm: 1; SizeY_mm: 0.5; SizeZ_mm: 0.6; Value2: 0.1W; CompType: Resistor; AEC Qualified: Y; VDC_V: 50V; AEC Grade: 0; AEC Category: Q200
R26 = CMP-0026329-2: RES, 3.01 k, 1%, 0.063 W, AEC-Q200 Grade 0, 0402; Manufacturer: Vishay-Dale; Power_W: 63mW; TempCo: 100 ppm/C; Value_Code: 3k01; Value: 3.01k; EIA_Code: E96; SizeX_mm: 1; SizeY_mm: 0.5; SizeZ_mm: 0.6; Value2: 0.063W; CompType: Resistor; AEC Qualified: Y; VDC_V: 50V; AEC Category: Q200; AEC Grade: 0
R27 = CMP-0026022-3: RES, 150, 1%, 0.063 W, AEC-Q200 Grade 0, 0402; Manufacturer: Vishay-Dale; Power_W: 63mW; TempCo: 100 ppm/C; Value_Code: 150R; Value: 150; EIA_Code: E96; SizeX_mm: 1; SizeY_mm: 0.5; SizeZ_mm: 0.6; Value2: 0.063W; AEC Qualified: Y; VDC_V: 50V; AEC Category: Q200; AEC Grade: 0
R28 = CMP-0026196-2: RES, 24.9 k, 1%, 0.063 W, AEC-Q200 Grade 0, 0402; Manufacturer: Vishay-Dale; Power_W: 63mW; TempCo: 100 ppm/C; Value_Code: 24k9; Value: 24.9k; EIA_Code: E96; SizeX_mm: 1; SizeY_mm: 0.5; SizeZ_mm: 0.6; Value2: 0.063W; CompType: Resistor; AEC Qualified: Y; VDC_V: 50V; AEC Category: Q200; AEC Grade: 0
R29 = CMP-0026859-2: RES, 1.0 M, 5%, 0.063 W, AEC-Q200 Grade 0, 0402; Manufacturer: Vishay-Dale; CompType: Resistor; Value: 1.0Meg; Res_ohm: 1M; Value_Code: 1M00; Power_W: 63mW; Value2: 0.063W; VDC_V: 50V; TempCo: 200 ppm/C; SizeArea_mm2: 0.5; SizeX_mm: 1; SizeZ_mm: 0.6; EIA_Code: E24; AEC Category: Q200; AEC Qualified: Y; AEC Grade: 0
R30 = CMP-0026327-2: RES, 39.2 k, 1%, 0.063 W, AEC-Q200 Grade 0, 0402; Manufacturer: Vishay-Dale; Power_W: 63mW; TempCo: 100 ppm/C; Value_Code: 39k2; Value: 39.2k; EIA_Code: E96; SizeX_mm: 1; SizeY_mm: 0.5; SizeZ_mm: 0.6; Value2: 0.063W; CompType: Resistor; AEC Qualified: Y; VDC_V: 50V; AEC Category: Q200; AEC Grade: 0
R32 = CMP-0026027-3: RES, 15.0 k, 1%, 0.063 W, AEC-Q200 Grade 0, 0402; Manufacturer: Vishay-Dale; Power_W: 63mW; TempCo: 100 ppm/C; Value_Code: 15k0; Value: 15.0k; EIA_Code: E96; Res_ohm: 15k; SizeX_mm: 1; SizeY_mm: 0.5; SizeZ_mm: 0.6; Value2: 0.063W; CompType: Resistor; AEC Qualified: Y; VDC_V: 50V; AEC Category: Q200; AEC Grade: 0
R33 = CMP-0026435-2: RES, 511 k, 1%, 0.063 W, AEC-Q200 Grade 0, 0402; Manufacturer: Vishay-Dale; Power_W: 63mW; TempCo: 100 ppm/C; Value: 511k; EIA_Code: E96; SizeX_mm: 1; SizeY_mm: 0.5; SizeZ_mm: 0.6; Value2: 0.063W; AEC Qualified: Y; VDC_V: 50V; AEC Category: Q200; AEC Grade: 0
R101 = CMP-0025950-3: RES, 100 k, 1%, 0.063 W, AEC-Q200 Grade 0, 0402; Manufacturer: Vishay-Dale; Power_W: 63mW; TempCo: 100 ppm/C; Value: 100k; EIA_Code: E96; SizeX_mm: 1; SizeY_mm: 0.5; SizeZ_mm: 0.6; Value2: 0.063W; AEC Qualified: Y; VDC_V: 50V; AEC Category: Q200; AEC Grade: 0
R103 = CMP-0026280-2: RES, 301 k, 1%, 0.063 W, AEC-Q200 Grade 0, 0402; Manufacturer: Vishay-Dale; Power_W: 63mW; TempCo: 100 ppm/C; Value: 301k; EIA_Code: E96; SizeX_mm: 1; SizeY_mm: 0.5; SizeZ_mm: 0.6; Value2: 0.063W; AEC Qualified: Y; VDC_V: 50V; AEC Category: Q200; AEC Grade: 0
R104 = CMP-0026100-2: RES, 1.00 M, 1%, 0.063 W, AEC-Q200 Grade 0, 0402; Manufacturer: Vishay-Dale; Power_W: 63mW; TempCo: 100 ppm/C; Value_Code: 1M00; Value: 1.00Meg; EIA_Code: E96; Res_ohm: 1M; SizeX_mm: 1; SizeY_mm: 0.5; SizeZ_mm: 0.6; Value2: 0.063W; AEC Qualified: Y; VDC_V: 50V; AEC Category: Q200; AEC Grade: 0
RT1 = CMP-0002532-2: Thermistor NTC, 100k ohm, 5%, 0805; Manufacturer: MuRata; TaMax_C: 125°C; SizeX_mm: 2; SizeY_mm: 1.25; TaMin_C: -40°C; Power_W: 200mW; SizeZ_mm: 1.45; SizeArea_mm2: 2.5; SizeAreaWB_mm2: 6.75; U/M: EA
T1 = CMP-0081439-3: Transformer, 110 uH, TH; Manufacturer: Renco Electronics; AEC Qualified: N; AEC Category: Q200; DCR_ohm: 0.15; SizeArea_mm2: 759.1581591; SizeX_mm: 23.749; Lp: 110; SizeZ_mm: 16.764; SizeY_mm: 31.9659; SizeAreaWB_mm2: 874.5879591; Ns1toNp: 0.2; LeakageInd_H: 2µH; Ind_H: 110µH; Value: 110uH; Rsec1_ohm: 6m
TP1 = CMP-0055148-1: Test Point, Multipurpose, Black, TH; Manufacturer: Keystone; PartNumber: 5011; CNHeader: FALSE; Green_Lifecycle: Active; Green_REACh: Passed; ContactFinish: Silver; CT: TRUE
TP2 = CMP-0055149-1: Test Point, Multipurpose, White, TH; Manufacturer: Keystone; PartNumber: 5012; CNHeader: FALSE; Green_Lifecycle: Active; Green_REACh: Passed; ContactFinish: Silver; CT: TRUE
U1 = CMP-0066933-1: 50-mA 40-V Voltage-Tracking LDO With 5-mV Tracking Tolerance, DBV0005A (SOT-23-5); Alternate Manufacturer: Texas Instruments; SizeAreaWB_mm2: 14.82; U/M: EA; SizeZ_mm: 1.45; SizeX_mm: 2.8; SizeY_mm: 2.9; SizeArea_mm2: 8.12; CompType: IC
U2 = CMP-0014005-4: Active-Clamp Flyback Controller, RTE0016C (WQFN-16); Manufacturer: Texas Instruments; SizeZ_mm: 0.8; SizeX_mm: 3; SizeArea_mm2: 9; CompType: IC; U/M: EA; SizeAreaWB_mm2: 16
U3 = CMP-0065069-2: 620-V High-Side Low-Side Gate Driver with 0.5/1.0A Peak Output and RobustDrive, D0008B (SOIC-8); Manufacturer: Texas Instruments; SizeX_mm: 6.0; SizeY_mm: 4.9; CompType: IC; SizeZ_mm: 1.75; SizeArea_mm2: 29.4; SizeAreaWB_mm2: 55.2; U/M: EA
U4 = CMP-0006160-3: Optocoupler, 5 kV, 63-125% CTR, SMT; Manufacturer: Vishay-Semiconductor; CTR (Max): 125%; SizeAreaWB_mm2: 74.42; CTR (Min): 63%; SizeZ_mm: 2.3; SizeX_mm: 10.2; SizeY_mm: 4.1; SizeArea_mm2: 41.82; Voltage_Isolation_Vrms: 5kV
U5 = CMP-0066199-1: 2.5V Low Iq Adjustable Precision Shunt Regulator, DBZ0003A (SOT-23-3); Manufacturer: Texas Instruments; SizeArea_mm2: 7.5; SizeAreaWB_mm2: 14.0; SizeX_mm: 2.5; SizeY_mm: 3.0; SizeZ_mm: 1.12; CompType: IC; U/M: EA

## Sheet PMP21479_REVE_Secondary.SchDoc
size 431 x 279 mm; Date: Not shown in title block; ApprovedBy: Not shown in title block; CheckedBy: Not shown in title block; Author: Not shown in title block; CompanyName: Not shown in title block; Engineer: Not shown in title block; Organization: Not shown in title block; Address1: Not shown in title block; Address2: Not shown in title block; Address3: Not shown in title block; Address4: Not shown in title block; DocumentNumber: 2; Revision: Use project parameter SCH_Rev; SheetNumber: 2; SheetTotal: 2; PageSetup: Record=PageOptions¦CenterHorizontal=True¦CenterVertical=True¦PrintScale=1.00¦XCorrection=1.00¦YCorrection=1.00¦PrintKind=0¦BorderSize=5000000¦LeftOffset=0¦BottomOffset=0¦Orientation=2¦PaperLength=1000¦PaperWidth=1000¦Scale=100¦PaperSource=15¦PrintQuality=600¦MediaType=1¦DitherType=10¦PaperKind=Letter¦PrintScaleMode=1
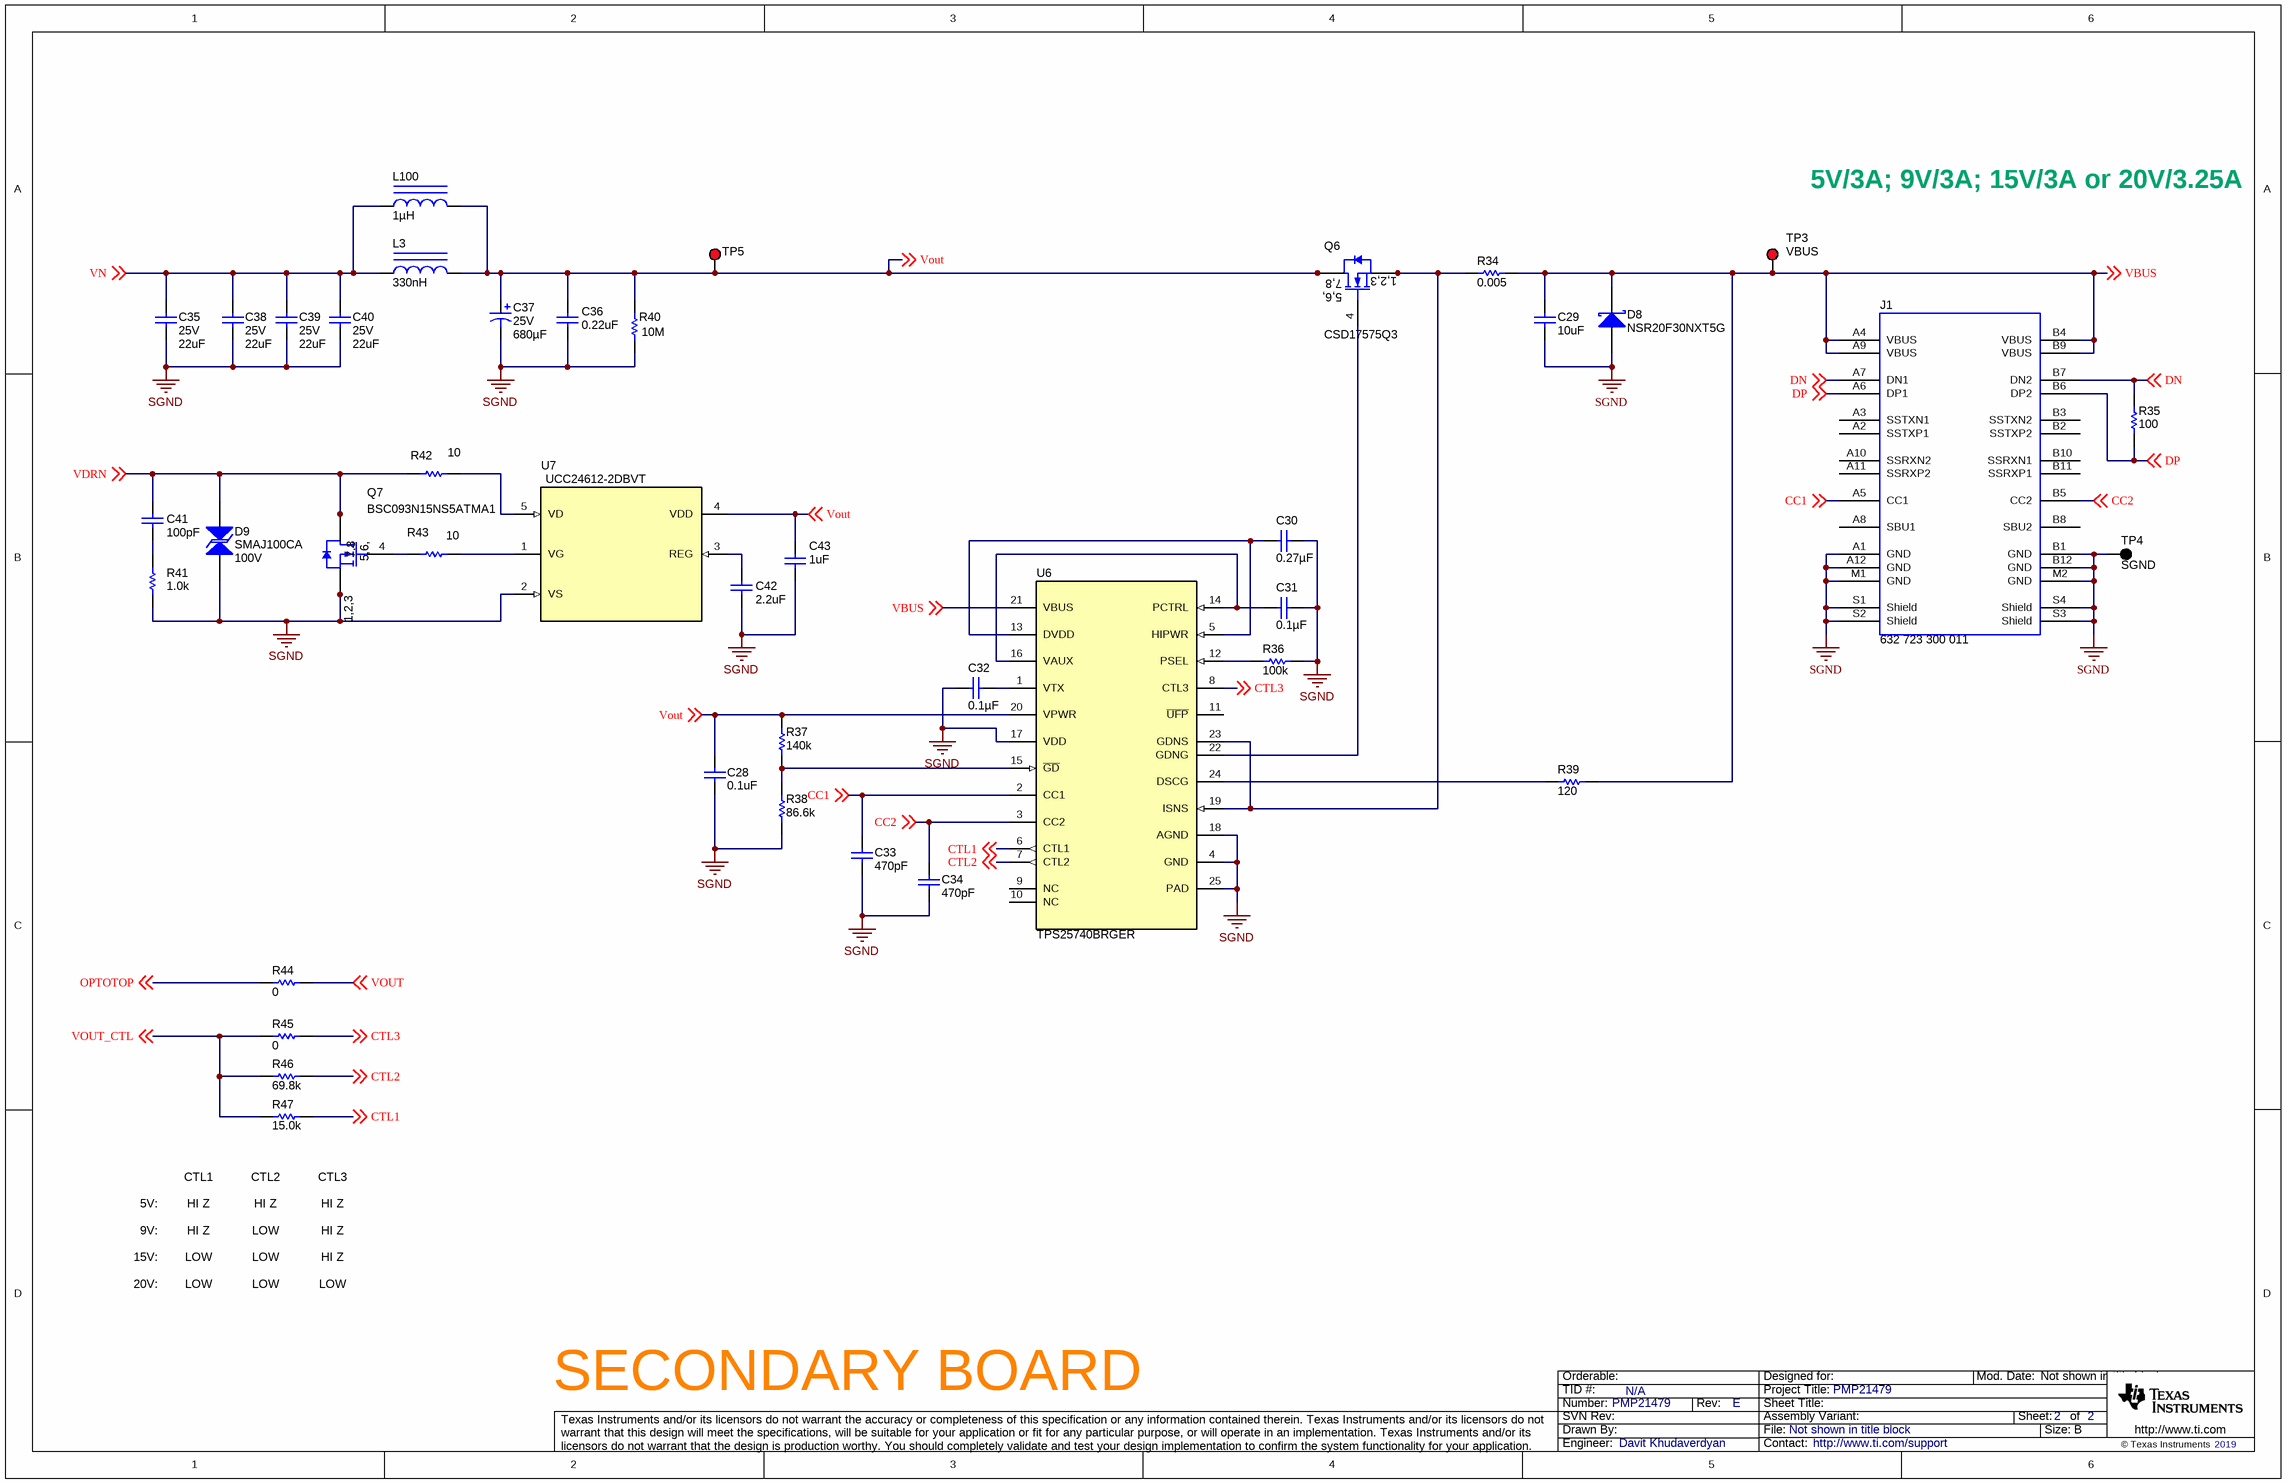
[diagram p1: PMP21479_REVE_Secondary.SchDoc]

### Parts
C28  ValueDisplayed: 0.1uF  [0402S]  (hidden comment: GRM155R71E104KE14D)
C29  ValueDisplayed: 10uF  [0805L]  (hidden comment: GRM21BR6YA106KE43L)
C30  ValueDisplayed: 0.27µF  [0402S]  (hidden comment: GRM155R60J274KE01D)
C31  ValueDisplayed: 0.1µF  [0402S]  (hidden comment: GRM155R71C104KA88D)
C32  ValueDisplayed: 0.1µF  [0402S]  (hidden comment: GRM155R71C104KA88D)
C33  ValueDisplayed: 470pF  [0402S]  (hidden comment: GRM155R71H471KA01D)
C34  ValueDisplayed: 470pF  [0402S]  (hidden comment: GRM155R71H471KA01D)
C35  VDC_V: 25V  ValueDisplayed: 22uF  [1210_270L]  (hidden comment: GRM32ER71E226KE15L)
C36  ValueDisplayed: 0.22uF  [1206L]  (hidden comment: GRM31MR71H224KA01L)
C37  VDC_V: 25V  ValueDisplayed: 680µF  [AVG_1000x1200_HD]  (hidden comment: 687AVG025MGBJ)
C38  VDC_V: 25V  ValueDisplayed: 22uF  [1210_270L]  (hidden comment: GRM32ER71E226KE15L)
C39  VDC_V: 25V  ValueDisplayed: 22uF  [1210_270L]  (hidden comment: GRM32ER71E226KE15L)
C40  VDC_V: 25V  ValueDisplayed: 22uF  [1210_270L]  (hidden comment: GRM32ER71E226KE15L)
C41  ValueDisplayed: 100pF  [0805]  (hidden comment: GRM21A5C2E101JW01D)
C42  ValueDisplayed: 2.2uF  [0805L]  (hidden comment: GRM21BR71E225KA73L)
C43  ValueDisplayed: 1uF  [0603S]  (hidden comment: C1608X7R1E105K080AB)
D8  NSR20F30NXT5G  [DSN2_0603]
D9  SMAJ100CA  value 100V  [SMA]
J1  632 723 300 011  [Wurth_632_723_300_011]
L3  ValueDisplayed: 330nH  [0630CDMCCDS]  (hidden comment: 0630CDMCCDS-R33MC)
L100  ValueDisplayed: 1µH  [0805]  (hidden comment: LBR2012T1R0M)
Q6  CSD17575Q3  [DQG0008A]
Q7  BSC093N15NS5ATMA1  [PG-TDSON-8]
R34  ValueDisplayed: 0.005  [1206L]  (hidden comment: WSL12065L000FEA)
R35  ValueDisplayed: 100  [0402S]  (hidden comment: CRCW0402100RJNED)
R36  ValueDisplayed: 100k  [0402S]  (hidden comment: CRCW0402100KFKED)
R37  ValueDisplayed: 140k  [0402S]  (hidden comment: CRCW0402140KFKED)
R38  ValueDisplayed: 86.6k  [0402S]  (hidden comment: CRCW040286K6FKED)
R39  ValueDisplayed: 120  [0805_HV1]  (hidden comment: RG2012P-121-B-T5)
R40  ValueDisplayed: 10M  [0603S]  (hidden comment: CRCW060310M0JNEA)
R41  ValueDisplayed: 1.0k  [1206L]  (hidden comment: CRCW12061K00JNEA)
R42  ValueDisplayed: 10  [0402S]  (hidden comment: CRCW040210R0JNED)
R43  ValueDisplayed: 10  [0402S]  (hidden comment: CRCW040210R0JNED)
R44  ValueDisplayed: 0  [0402S]  (hidden comment: RC0402JR-070RL)
R45  ValueDisplayed: 0  [0402S]  (hidden comment: RC0402JR-070RL)
R46  ValueDisplayed: 69.8k  [0402L]  (hidden comment: CRCW040269K8FKED)
R47  ValueDisplayed: 15.0k  [0402L]  (hidden comment: CRCW040215K0FKED)
TP3  VBUS  [Keystone5010]
TP4  SGND  [Keystone5011]
TP5  Vout  [Keystone5010]  (value not drawn)
U6  TPS25740BRGER  [RGE0024H]
U7  UCC24612-2DBVT  [DBV0005A_N]

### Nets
SGND: C28.2 C29.2 C30.2 C31.2 C32.2 C33.2 C34.2 C35.2 C36.2 C37.2(-) C38.2 C39.2 C40.2 C42.1 C43.2 D8.2(A) D9.2 J1.A1(GND) J1.A12(GND) J1.B1(GND) J1.B12(GND) J1.M1(GND) J1.M2(GND) J1.S1(Shield) J1.S2(Shield) J1.S3(Shield) J1.S4(Shield) Q7.1(S) Q7.2(S) Q7.3(S) R36.1 R38.1 R40.1 R41.1 TP4.1 U6.4(GND) U6.17(VDD) U6.18(AGND) U6.25(PAD) U7.2(VS)
CC1: C33.1 J1.A5(CC1) U6.2(CC1) ; off-sheet CC1
CC2: C34.1 J1.B5(CC2) U6.3(CC2) ; off-sheet CC2
CTL1: R47.2 U6.6(CTL1) ; off-sheet CTL1
CTL2: R46.2 U6.7(CTL2) ; off-sheet CTL2
CTL3: R45.1 U6.8(CTL3) ; off-sheet CTL3
DN: J1.A7(DN1) J1.B7(DN2) R35.1 ; off-sheet DN
DP: J1.A6(DP1) J1.B6(DP2) R35.2 ; off-sheet DP
OPTOTOP: R44.2 ; off-sheet OPTOTOP
VBUS: C29.1 D8.1(K) J1.A4(VBUS) J1.A9(VBUS) J1.B4(VBUS) J1.B9(VBUS) R34.1 R39.2 TP3.1 U6.21(VBUS) ; off-sheet VBUS
VDRN: C41.1 D9.1 Q7.5(D) Q7.6(D) Q7.7(D) Q7.8(D) Q7.9(D) R42.2 ; off-sheet VDRN
VN: C35.1 C38.1 C39.1 C40.1 L3.1 L100.1 ; off-sheet VN
Vout: C28.1 C36.1 C37.1(+) C43.1 L3.2 L100.2 Q6.5(D) Q6.6(D) Q6.7(D) Q6.8(D) Q6.9(D) R37.2 R40.2 R44.1 TP5.1 U6.20(VPWR) U7.4(VDD) ; off-sheet Vout, off-sheet VOUT
VOUT_CTL: R45.2 R46.1 R47.1 ; off-sheet VOUT_CTL
NetC30_1: C30.1 U6.5(HIPWR) U6.13(DVDD)
NetC31_1: C31.1 U6.14(PCTRL) U6.16(VAUX)
NetC32_1: C32.1 U6.1(VTX)
NetC41_2: C41.2 R41.2
NetC42_2: C42.2 U7.3(REG)
NetQ6_1: Q6.1(S) Q6.2(S) Q6.3(S) R34.2 U6.19(ISNS) U6.23(GDNS)
NetQ6_4: Q6.4(G) U6.22(GDNG)
NetQ7_4: Q7.4(G) R43.2
NetR36_2: R36.2 U6.12(PSEL)
NetR37_1: R37.1 R38.2 U6.15(~{GD})
NetR39_1: R39.1 U6.24(DSCG)
NetR42_1: R42.1 U7.5(VD)
NetR43_1: R43.1 U7.1(VG)

Not connected (* = marked no-connect by the designer): J1 A2(SSTXP1) A3(SSTXN1) A8(SBU1) A10(SSRXN2) A11(SSRXP2) B2(SSTXP2) B3(SSTXN2) B8(SBU2) B10(SSRXN1) B11(SSRXP1); U6 9(NC) 10(NC) 11(~{UFP})

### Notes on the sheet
- 5V/3A; 9V/3A; 15V/3A or 20V/3.25A
- 5V:
- 9V:
- CTL1
- HI Z
- CTL2
- LOW
- CTL3
- 15V:
- 20V:
- SECONDARY BOARD

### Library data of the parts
C28 = CMP-0006659-2: as C17 on sheet PMP21479_REVE_Primary
C29 = CMP-0008310-1: CAP, CERM, 10 uF, 35 V, +/- 10%, X5R, 0805; Manufacturer: MuRata; TaMin_C: -55°C; Polarized: N; SizeAreaWB_mm2: 6.75; Value1: Unknown; U/M: EA; Value: 10uF; TaMax_C: 85°C; SizeZ_mm: 1.45; SizeX_mm: 2; SizeY_mm: 1.25; Cap_Case: 0805; Value2: 35V; SizeArea_mm2: 2.5; Cap_F: 10µF; AEC Category: Q200
C30 = GRM155R60J274KE01D: CAP, CERM, 0.27 µF, 6.3 V, +/- 10%, X5R, 0402; Manufacturer: MuRata; Polarized: N; CompType: Capacitor; Value: 0.27uF; U/M: EA; Cap_F: 0.00000027; Tolerance_%: 10; Value1: Unknown; VDC_V: 6.3; Value2: 6.3V; TaMin_C: -55; TaMax_C: 85; Cap_Case: 0402
C31 C32 = GRM155R71C104KA88D: CAP, CERM, 0.1 µF, 16 V, +/- 10%, X7R, 0402; Manufacturer: MuRata; Polarized: N; CompType: Capacitor; Value: 0.1uF; U/M: EA; Cap_F: 0.0000001; Tolerance_%: 10; Value1: Unknown; VDC_V: 16; Value2: 16V; TaMin_C: -55; TaMax_C: 125; Cap_Case: 0402
C33 C34 = GRM155R71H471KA01D: CAP, CERM, 470 pF, 50 V, +/- 10%, X7R, 0402; Manufacturer: MuRata; Polarized: N; CompType: Capacitor; Value: 470pF; U/M: EA; Cap_F: 0.00000000047; Tolerance_%: 10; Value1: Unknown; VDC_V: 50; Value2: 50V; TaMin_C: -55; TaMax_C: 125; Cap_Case: 0402
C35 C38-C40 = CMP-0009224-2: CAP, CERM, 22 uF, 25 V, +/- 10%, X7R, 1210; Manufacturer: MuRata; TaMin_C: -55°C; Polarized: N; SizeAreaWB_mm2: 14.7; Value1: Unknown; U/M: EA; Value: 22uF; TaMax_C: 125°C; SizeZ_mm: 2.7; SizeX_mm: 3.2; SizeY_mm: 2.5; Cap_Case: 1210; SizeArea_mm2: 8; Cap_F: 22µF; AEC Category: Q200
C36 = CMP-0008995-2: CAP, CERM, 0.22 uF, 50 V, +/- 10%, X7R, 1206; Manufacturer: MuRata; TaMin_C: -55°C; Polarized: N; SizeAreaWB_mm2: 10.92; Value1: Unknown; U/M: EA; Value: 0.22uF; TaMax_C: 125°C; SizeZ_mm: 1.35; SizeX_mm: 3.2; SizeY_mm: 1.6; Cap_Case: 1206; Value2: 50V; SizeArea_mm2: 5.12; CompType: Capacitor; Cap_F: 220nF; AEC Category: Q200
C37 = CMP-0081668-2: CAP, Aluminum Polymer, 680 µF, 25 V,+/- 20%, 0.29256 ohm, TH; Manufacturer: Illinois Capacitor; CompType: Capacitor; Cap_Case: 10x12mm; AEC Qualified: N; AEC Category: Q200; SizeArea_mm2: 100; SizeAreaWB_mm2: 144; Polarized: Y; SizeZ_mm: 13.5; SizeX_mm: 10; TaMax_C: 125°C; Value: 680uF; IRMS_A: 4.7A; TaMin_C: -55°C
C41 = CMP-0008236-2: CAP, CERM, 100 pF, 250 V, +/- 5%, C0G/NP0, 0805; Manufacturer: MuRata; Polarized: N; CompType: Capacitor; Value: 100pF; U/M: EA; Value1: Unknown; VDC_V: 250V; TaMin_C: -55°C; TaMax_C: 125°C; SizeArea_mm2: 2.5; SizeAreaWB_mm2: 6.75; SizeX_mm: 2; SizeY_mm: 1.25; SizeZ_mm: 1.45; AEC Category: Q200
C42 = CMP-0008342-2: CAP, CERM, 2.2 uF, 25 V, +/- 10%, X7R, 0805; Manufacturer: MuRata; TaMin_C: -55°C; ESR_ohm: 5m; Polarized: N; SizeAreaWB_mm2: 6.75; Value1: 0.005 ohm; U/M: EA; Value: 2.2uF; TaMax_C: 125°C; SizeZ_mm: 1.45; SizeX_mm: 2; SizeY_mm: 1.25; Cap_Case: 0805; Value2: 25V; SizeArea_mm2: 2.5; CompType: Capacitor; Cap_F: 2.2µF; AEC Category: Q200
C43 = CMP-0007040-4: as C10 on sheet PMP21479_REVE_Primary
D8 = CMP-0028829-1: Diode, Schottky, 30 V, 2 A, 2-XFDFN; Manufacturer: ON Semiconductor; Io_A: 2A; Green_Lifecycle: Not Set; SizeAreaWB_mm2: 4.68; Vr_V: 30V; Green_REACh: Incomplete; TJmax_C: 150°C; U/M: EA; Value: 30V; SizeZ_mm: 0.31; SizeX_mm: 1.6; SizeY_mm: 0.8; Vf_V: 4.8dV; Value2: 0.48V; SizeArea_mm2: 1.28; AEC Qualified: N; AEC Category: Q101
D9 = CMP-0005466-2: Diode, TVS, Bi, 100 V, SMA; Manufacturer: Littelfuse; Power_W: 3.3W; SizeAreaWB_mm2: 37.3428; RJA_CperW: 120; U/M: EA; SizeZ_mm: 2.87; SizeX_mm: 5.59; SizeY_mm: 2.92; SizeArea_mm2: 16.3228; AEC Category: Q101
J1 = CMP-0054818-1: Connector, Receptacle, USB Type C, R/A; Manufacturer: Wurth Elektronik; CNHeader: FALSE; Current_A: 3A; Gender: Female; Voltage_V: 5V; ContactFinish: Gold; CT: TRUE; Cert_UL: Y
L3 = CMP-0062208-1: Inductor, Shielded, Metal Composite, 330 nH, 21 A, 0.0035 ohm, SMD; Manufacturer: Sumida; Isat: 32.3A @ 30% inductance drop; Irms: 24A @ 40C rise; SizeAreaWB_mm2: 77.4; DCR_ohm: 3m; Value1: 0.003 ohm; Value: 330nH; Imax_A: 24A; SizeZ_mm: 3; SizeX_mm: 7; SizeY_mm: 6.6; SizeArea_mm2: 46.2; AEC Qualified: N; AEC Category: Q200
L100 = CMP-0086281-1: Inductor, Wirewound, 1 µH, 0.4 A, 0.091 ohm, SMD; Manufacturer: Taiyo Yuden; AEC Category: Q200; SizeY_mm: 1.25; Value: 1uH; SizeX_mm: 2; SizeAreaWB_mm2: 6.75; SizeZ_mm: 1.45; SizeArea_mm2: 2.5; DCR_ohm: 0.091; Imax_A: 400mA; Value2: 0.4A; AEC Qualified: N
Q6 = CSD17575Q3: MOSFET, N-CH, 30 V, 60 A, DQG0008A; Manufacturer: Texas Instruments; Alternate Manufacturer: None; U/M: EA; ChType: N; Value: 30V; VdsMax_V: 30; Value1: 0.0032 ohm; Rdson45_ohm: 0.0032; Value2: 23 nC; QgTyp_nC: 23; Vgs_V: 20; IdsMax_A: 60; AEC Category: Q101
Q7 = CMP-0001046-2: MOSFET, N-CH, 150 V, 87 A, PG-TDSON-8; Alternate Manufacturer: None; Manufacturer: Infineon Technologies; SizeZ_mm: 1.12; ChType: N; Value2: 33 nC; VdsMax_V: 150V; SizeX_mm: 5.99; SizeY_mm: 4.9; Vgs_V: 20V; QgTyp_nC: 33; Value: 150V; SizeArea_mm2: 29.351; AEC Category: Q101; IdsMax_A: 87A; SizeAreaWB_mm2: 55.131; U/M: EA
R34 = WSL12065L000FEA: RES, 0.005, 1%, 0.25 W, 1206; Manufacturer: Vishay-Dale; CompType: Resistor; Value: 0.005; Value_Code: 5L000; Tolerance_%: 1; Power_W: 0.25; Value2: 0.25W; TempCo: 110 ppm/C; EIA_Code: E96; U/M: EA; SizeArea_mm2: 5.12; SizeX_mm: 3.2; SizeY_mm: 1.6; SizeZ_mm: 1.35; AEC Category: Q200; AEC Qualified: N
R35 = CRCW0402100RJNED: RES, 100, 5%, 0.063 W, 0402; Manufacturer: Vishay-Dale; CompType: Resistor; Value: 100; Value_Code: 100R; Tolerance_%: 5; Power_W: 0.063; Value2: 0.063W; VDC_V: 50; TempCo: 200 ppm/C; EIA_Code: E24; U/M: EA; AEC Category: Q200
R36 = CRCW0402100KFKED: RES, 100 k, 1%, 0.063 W, 0402; Manufacturer: Vishay-Dale; CompType: Resistor; Value: 100k; Res_ohm: 100000; Tolerance_%: 1; Power_W: 0.063; Value2: 0.063W; VDC_V: 50; TempCo: 100 ppm/C; EIA_Code: E96; U/M: EA; AEC Category: Q200
R37 = CRCW0402140KFKED: RES, 140 k, 1%, 0.063 W, 0402; Manufacturer: Vishay-Dale; CompType: Resistor; Value: 140k; Res_ohm: 140000; Tolerance_%: 1; Power_W: 0.063; Value2: 0.063W; VDC_V: 50; TempCo: 100 ppm/C; EIA_Code: E96; U/M: EA; AEC Category: Q200
R38 = CRCW040286K6FKED: RES, 86.6 k, 1%, 0.063 W, 0402; Manufacturer: Vishay-Dale; CompType: Resistor; Value: 86.6k; Res_ohm: 86600; Value_Code: 86k6; Tolerance_%: 1; Power_W: 0.063; Value2: 0.063W; VDC_V: 50; TempCo: 100 ppm/C; EIA_Code: E96; U/M: EA; AEC Category: Q200
R39 = RG2012P-121-B-T5: RES, 120, 0.1%, 0.125 W, 0805; Manufacturer: Susumu Co Ltd; CompType: Resistor; Value: 120; Value_Code: 120R; Tolerance_%: 0.1; Power_W: 0.125; Value2: 0.125W; VDC_V: 100; TempCo: 25 ppm/C; EIA_Code: E192; U/M: EA
R40 = CMP-0025702-4: RES, 10 M, 5%, 0.1 W, AEC-Q200 Grade 0, 0603; Manufacturer: Vishay-Dale; CompType: Resistor; Value: 10Meg; Value_Code: 10M0; Power_W: 100mW; Value2: 0.1W; VDC_V: 75V; TempCo: 200 ppm/C; SizeArea_mm2: 1.28; SizeX_mm: 1.6; SizeY_mm: 0.8; SizeZ_mm: 1; EIA_Code: E24; AEC Category: Q200; AEC Qualified: Y; AEC Grade: 0
R41 = CMP-0018603-3: RES, 1.0 k, 5%, 0.25 W, AEC-Q200 Grade 0, 1206; Manufacturer: Vishay-Dale; CompType: Resistor; Value: 1.0k; Res_ohm: 1k; Value_Code: 1k00; Power_W: 250mW; Value2: 0.25W; VDC_V: 200V; TempCo: 200 ppm/C; SizeArea_mm2: 5.12; SizeX_mm: 3.2; SizeY_mm: 1.6; SizeZ_mm: 1.35; EIA_Code: E24; AEC Category: Q200; AEC Qualified: Y; AEC Grade: 0
R42 R43 = CMP-0026827-3: RES, 10, 5%, 0.063 W, AEC-Q200 Grade 0, 0402; Manufacturer: Vishay-Dale; CompType: Resistor; Value: 10; Value_Code: 10R0; Power_W: 63mW; Value2: 0.063W; VDC_V: 50V; TempCo: 200 ppm/C; SizeArea_mm2: 0.5; SizeX_mm: 1; SizeZ_mm: 0.6; EIA_Code: E24; AEC Category: Q200; AEC Qualified: Y; AEC Grade: 0
R44 R45 = CMP-0027004-2: RES, 0, 5%, 0.063 W, 0402; Manufacturer: Yageo America; Power_W: 63mW; TempCo: 200 ppm/C; Value_Code: 0000; U/M: EA; Value: 0; EIA_Code: E24; SizeX_mm: 1; SizeY_mm: 0.5; SizeZ_mm: 0.6; Value2: 0.063W; CompType: Resistor; VDC_V: 50V; AEC Category: Q200
R46 = CMP-0026510-2: RES, 69.8 k, 1%, 0.063 W, AEC-Q200 Grade 0, 0402; Manufacturer: Vishay-Dale; Power_W: 63mW; TempCo: 100 ppm/C; Value_Code: 69k8; Value: 69.8k; EIA_Code: E96; SizeX_mm: 1; SizeY_mm: 0.5; SizeZ_mm: 0.6; Value2: 0.063W; AEC Qualified: Y; VDC_V: 50V; AEC Category: Q200; AEC Grade: 0
R47 = CMP-0026027-3: RES, 15.0 k, 1%, 0.063 W, AEC-Q200 Grade 0, 0402; Manufacturer: Vishay-Dale; Power_W: 63mW; TempCo: 100 ppm/C; Value_Code: 15k0; Value: 15.0k; EIA_Code: E96; Res_ohm: 15k; SizeX_mm: 1; SizeY_mm: 0.5; SizeZ_mm: 0.6; Value2: 0.063W; AEC Qualified: Y; VDC_V: 50V; AEC Category: Q200; AEC Grade: 0
TP3 = CMP-0055147-1: Test Point, Multipurpose, Red, TH; Manufacturer: Keystone; PartNumber: 5010; CNHeader: FALSE; Green_Lifecycle: Active; Green_REACh: Passed; ContactFinish: Silver; CT: TRUE
TP4 = CMP-0055148-1: as TP1 on sheet PMP21479_REVE_Primary
TP5 = CMP-0055147-1: Test Point, Multipurpose, Red, TH; PartNumber: 5010; Manufacturer: Keystone; ContactFinish: Silver; CNHeader: FALSE; CT: TRUE; Green_Lifecycle: Active; Green_REACh: Passed
U6 = TPS25740BRGER: USB Type-C and USB PD Source Controller, RGE0024H (VQFN-24); Alternate PartNumber: TPS25740BRGET; Manufacturer: Texas Instruments; SymbolCreator: a0411947; SizeArea_mm2: 16; SizeAreaWB_mm2: 25; SizeX_mm: 4; SizeZ_mm: 1; CompType: IC; U/M: EA
U7 = CMP-0013047-3: High-Frequency Multi-Mode Synchronous Rectifier Controller, DBV0005A (SOT-23-5); Alternate PartNumber: UCC24612-2DBVR; Manufacturer: Texas Instruments; SizeArea_mm2: 8.12; SizeAreaWB_mm2: 14.82; SizeX_mm: 2.8; SizeY_mm: 2.9; SizeZ_mm: 1.45; CompType: IC; AEC Category: Q200; AEC Qualified: N

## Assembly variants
001: not fitted C20 C41 R29 R41 R104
